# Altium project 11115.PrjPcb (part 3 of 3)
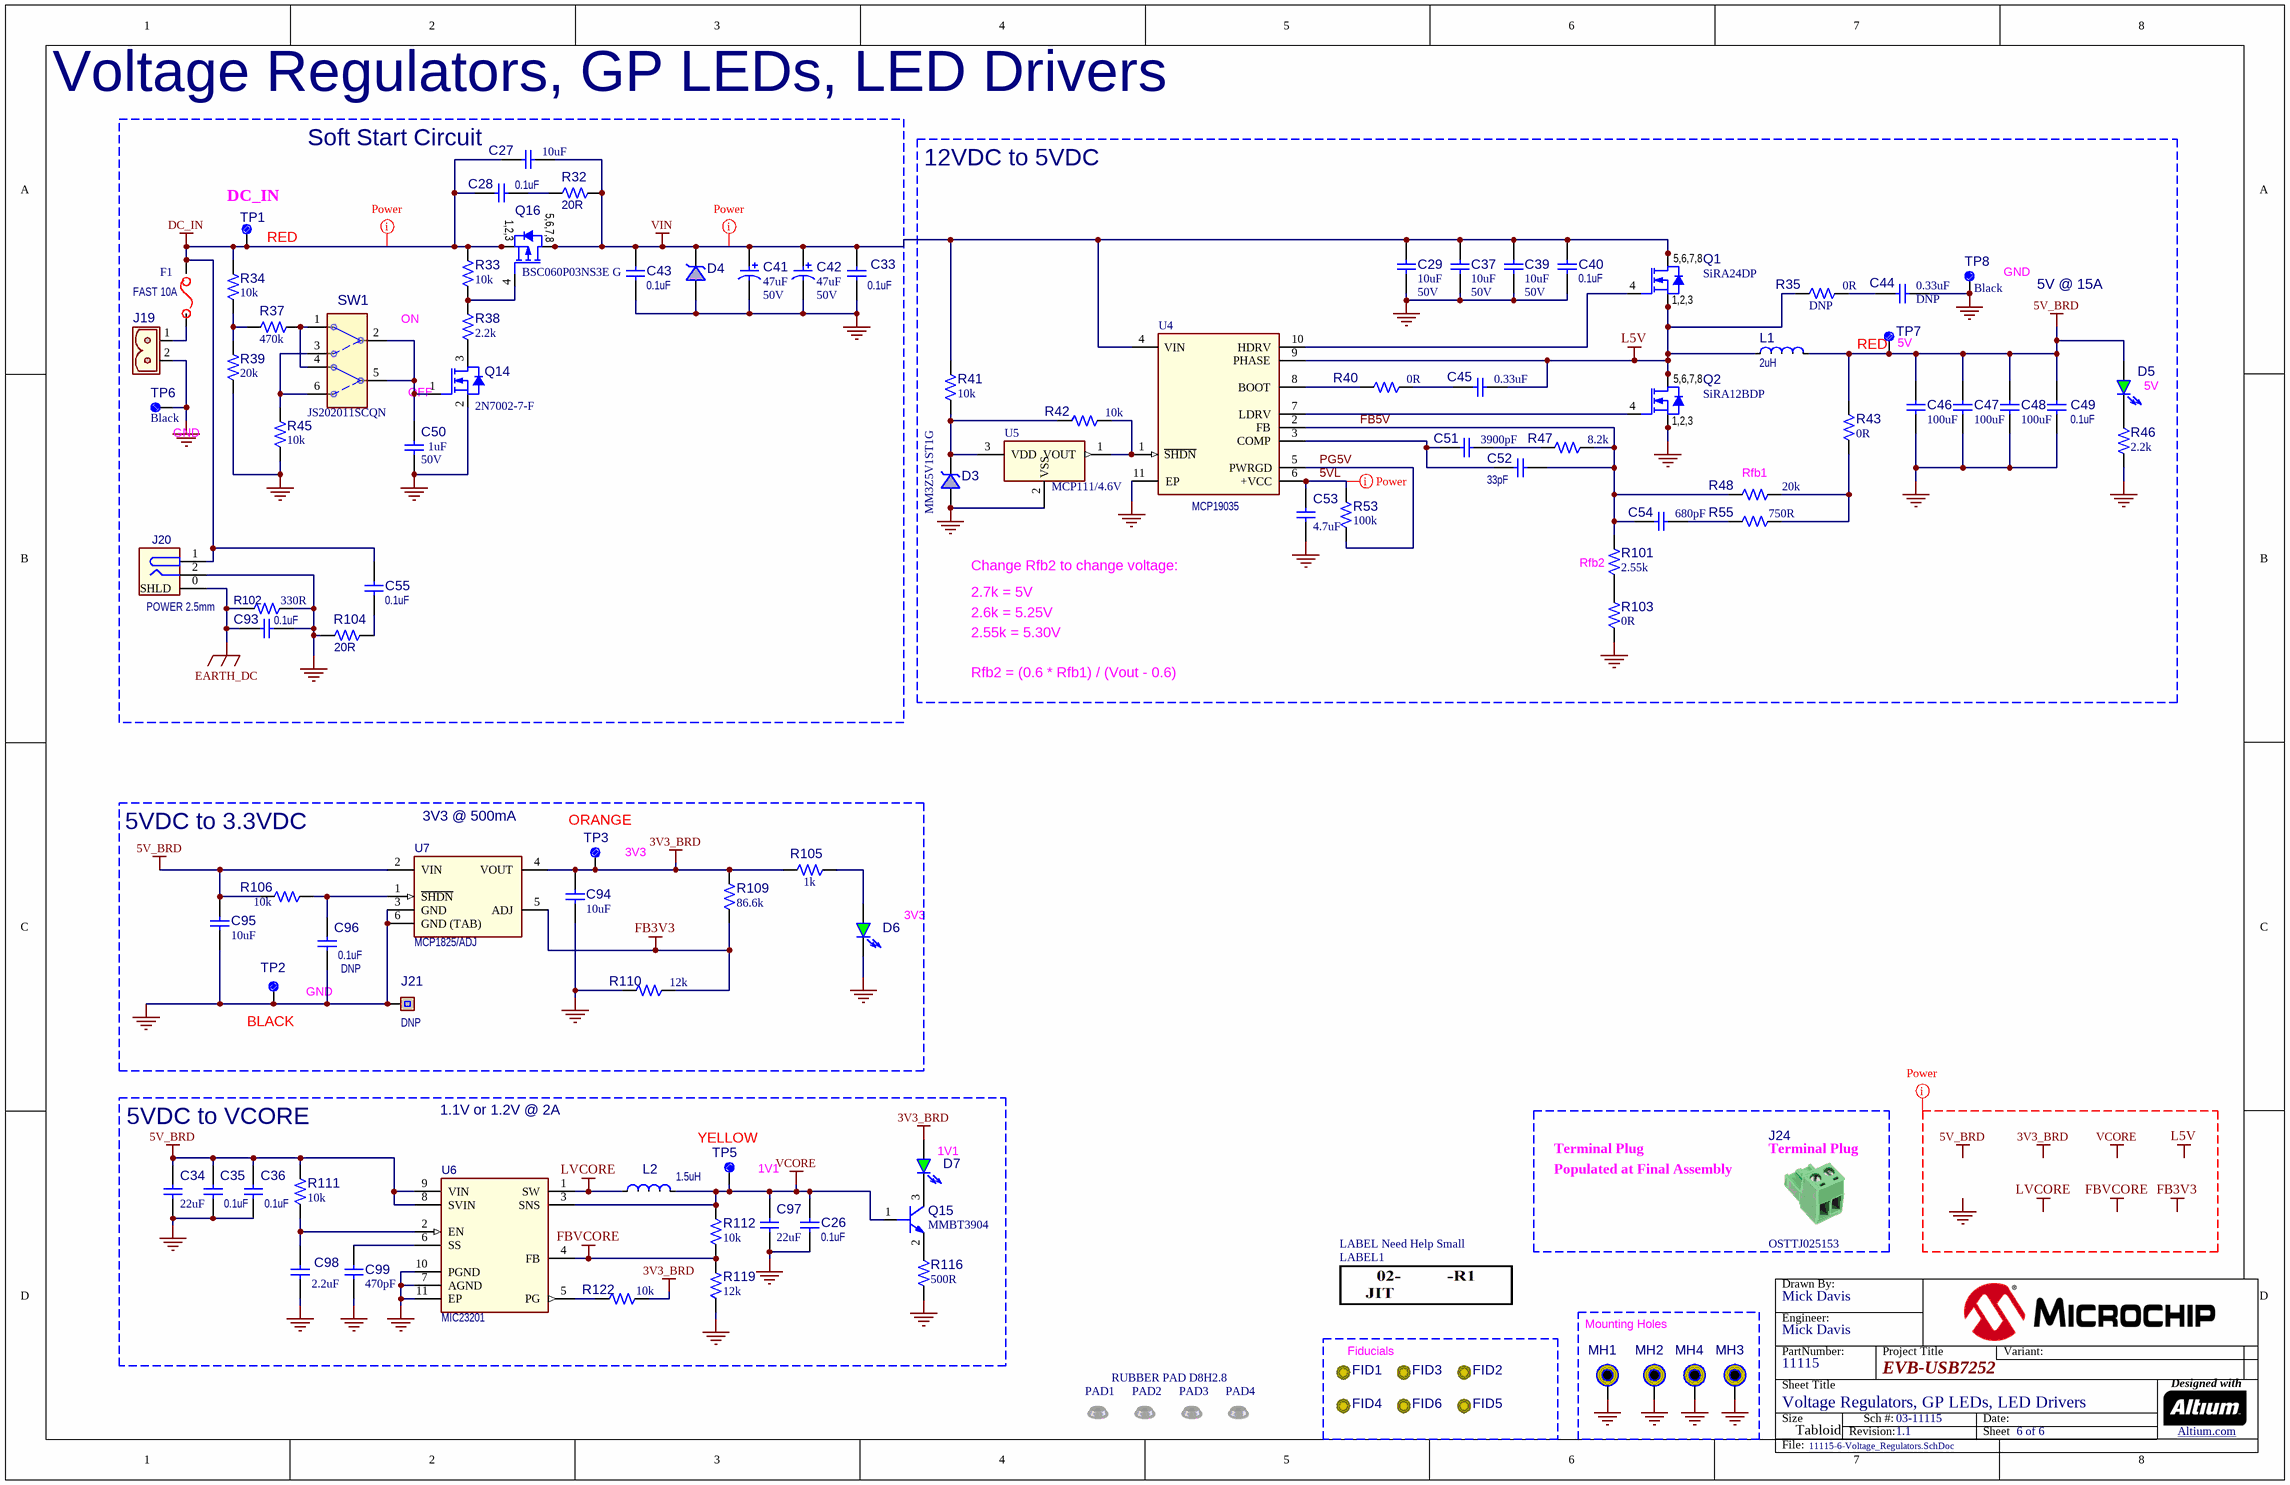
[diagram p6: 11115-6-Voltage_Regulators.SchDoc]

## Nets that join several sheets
3V3_BRD: 11115-2-USB7252 (32 pins), 11115-3-USB-B-Upstream (6 pins), 11115-4-USB-C Downstream 1-2 (D15.2 D16.2), 11115-6-Voltage_Regulators (7 pins)
5V_BRD: 11115-3-USB-B-Upstream (C60.1 J5.10 R58.1 U9.5), 11115-4-USB-C Downstream 1-2 (23 pins), 11115-5-USB-A Downstream 3-4 (13 pins), 11115-6-Voltage_Regulators (17 pins)
GND: 11115-2-USB7252 (39 pins), 11115-3-USB-B-Upstream (17 pins), 11115-4-USB-C Downstream 1-2 (47 pins), 11115-5-USB-A Downstream 3-4 (24 pins), 11115-6-Voltage_Regulators (59 pins)
VCORE: 11115-2-USB7252 (18 pins), 11115-6-Voltage_Regulators (7 pins)
BASIC_CC1_P1: 11115-2-USB7252 (U3.12), 11115-4-USB-C Downstream 1-2 (R2.1 R73.2)
BASIC_CC1_P2: 11115-2-USB7252 (U3.27), 11115-4-USB-C Downstream 1-2 (R68.1 R70.2)
BASIC_CC2_P1: 11115-2-USB7252 (U3.13), 11115-4-USB-C Downstream 1-2 (R67.1 R74.2)
BASIC_CC2_P2: 11115-2-USB7252 (U3.28), 11115-4-USB-C Downstream 1-2 (R1.1 R69.2)
DP1_DISCHARGE: 11115-2-USB7252 (R18.1), 11115-4-USB-C Downstream 1-2 (Q8.1 R85.2)
DP1_VBUS_MON: 11115-2-USB7252 (U3.4), 11115-4-USB-C Downstream 1-2 (C72.1 D16.3 R76.1 R82.2)
DP1_VCONN1: 11115-2-USB7252 (R15.1), 11115-4-USB-C Downstream 1-2 (Q13.1 R94.2)
DP1_VCONN2: 11115-2-USB7252 (R16.1), 11115-4-USB-C Downstream 1-2 (Q12.1 R93.2)
DP2_DISCHARGE: 11115-2-USB7252 (R17.1), 11115-4-USB-C Downstream 1-2 (Q7.1 R92.2)
DP2_VBUS_MON: 11115-2-USB7252 (U3.36), 11115-4-USB-C Downstream 1-2 (C70.1 D15.3 R75.2 R80.1)
DP2_VCONN1: 11115-2-USB7252 (R22.1), 11115-4-USB-C Downstream 1-2 (Q10.1 R90.2)
DP2_VCONN2: 11115-2-USB7252 (R23.1), 11115-4-USB-C Downstream 1-2 (Q11.1 R91.2)
MSTR_I2C_CLK: 11115-2-USB7252 (J13.1 R30.1 R100.1), 11115-3-USB-B-Upstream (J5.12)
MSTR_I2C_DATA: 11115-2-USB7252 (J13.3 R28.1 R99.1), 11115-3-USB-B-Upstream (J5.11)
PF7: 11115-2-USB7252 (U3.48), 11115-3-USB-B-Upstream (J5.15)
PF14: 11115-2-USB7252 (U3.57), 11115-3-USB-B-Upstream (J5.3)
PF19: 11115-2-USB7252 (J10.3 R95.1 U3.66), 11115-3-USB-B-Upstream (J5.4)
PF26: 11115-2-USB7252 (J10.1 R97.1 U3.75), 11115-3-USB-B-Upstream (J5.6)
PF27: 11115-2-USB7252 (U3.76), 11115-3-USB-B-Upstream (J5.1)
PF28: 11115-2-USB7252 (U3.77), 11115-3-USB-B-Upstream (J5.5)
PRT_CTL1: 11115-2-USB7252 (R25.1), 11115-4-USB-C Downstream 1-2 (R7.1 R8.1)
PRT_CTL2: 11115-2-USB7252 (R24.1), 11115-4-USB-C Downstream 1-2 (R9.2 R10.2)
PRT_CTL3: 11115-2-USB7252 (U3.56), 11115-5-USB-A Downstream 3-4 (U2.1 U2.20)
PRT_CTL4: 11115-2-USB7252 (U3.59), 11115-5-USB-A Downstream 3-4 (U2.15 U2.16)
RST_N: 11115-2-USB7252 (5 pins), 11115-3-USB-B-Upstream (J6.2)
SPI_CE/PF20: 11115-2-USB7252 (J14.4), 11115-3-USB-B-Upstream (R118.1 U8.1 U9.2)
SPI_CLK/PF21: 11115-2-USB7252 (U3.68), 11115-3-USB-B-Upstream (J15.4 R115.2 U8.6)
SPI_D2/PF24: 11115-2-USB7252 (U3.72), 11115-3-USB-B-Upstream (J15.1 R49.2)
SPI_D3/PF25: 11115-2-USB7252 (U3.73), 11115-3-USB-B-Upstream (J15.3 R51.2)
SPI_MISO/PF23: 11115-2-USB7252 (U3.71), 11115-3-USB-B-Upstream (R117.2 U8.2)
SPI_MOSI/PF22: 11115-2-USB7252 (J14.1), 11115-3-USB-B-Upstream (J15.2 U8.5)
USB2DN1/PRT_DIS_1_N: 11115-2-USB7252 (U3.6), 11115-4-USB-C Downstream 1-2 (J2.A7 J2.B7)
USB2DN1/PRT_DIS_1_P: 11115-2-USB7252 (U3.5), 11115-4-USB-C Downstream 1-2 (J2.A6 J2.B6)
USB2DN2/PRT_DIS_2_N: 11115-2-USB7252 (U3.30), 11115-4-USB-C Downstream 1-2 (J3.A7 J3.B7)
USB2DN2/PRT_DIS_2_P: 11115-2-USB7252 (U3.29), 11115-4-USB-C Downstream 1-2 (J3.A6 J3.B6)
USB2DN3/PRT_DIS_3_N: 11115-2-USB7252 (U3.82), 11115-5-USB-A Downstream 3-4 (J1.2)
USB2DN3/PRT_DIS_3_P: 11115-2-USB7252 (U3.81), 11115-5-USB-A Downstream 3-4 (J1.3)
USB2DN4/PRT_DIS_4_N: 11115-2-USB7252 (U3.15), 11115-5-USB-A Downstream 3-4 (J4.2)
USB2DN4/PRT_DIS_4_P: 11115-2-USB7252 (U3.14), 11115-5-USB-A Downstream 3-4 (J4.3)
USB2UP_N: 11115-2-USB7252 (U3.90), 11115-3-USB-B-Upstream (J22.2)
USB2UP_P: 11115-2-USB7252 (U3.89), 11115-3-USB-B-Upstream (J22.3)
USB3DN_RX1A_N: 11115-2-USB7252 (U3.11), 11115-4-USB-C Downstream 1-2 (J2.B10)
USB3DN_RX1A_P: 11115-2-USB7252 (U3.10), 11115-4-USB-C Downstream 1-2 (J2.B11)
USB3DN_RX1B_N: 11115-2-USB7252 (U3.19), 11115-4-USB-C Downstream 1-2 (J2.A10)
USB3DN_RX1B_P: 11115-2-USB7252 (U3.20), 11115-4-USB-C Downstream 1-2 (J2.A11)
USB3DN_RX2A_N: 11115-2-USB7252 (U3.35), 11115-4-USB-C Downstream 1-2 (J3.B10)
USB3DN_RX2A_P: 11115-2-USB7252 (U3.34), 11115-4-USB-C Downstream 1-2 (J3.B11)
USB3DN_RX2B_N: 11115-2-USB7252 (U3.40), 11115-4-USB-C Downstream 1-2 (J3.A10)
USB3DN_RX2B_P: 11115-2-USB7252 (U3.41), 11115-4-USB-C Downstream 1-2 (J3.A11)
USB3DN_RX3_N: 11115-2-USB7252 (U3.87), 11115-5-USB-A Downstream 3-4 (J1.5)
USB3DN_RX3_P: 11115-2-USB7252 (U3.86), 11115-5-USB-A Downstream 3-4 (J1.6)
USB3DN_TX1A_N: 11115-2-USB7252 (U3.8), 11115-4-USB-C Downstream 1-2 (C10.1)
USB3DN_TX1A_P: 11115-2-USB7252 (U3.7), 11115-4-USB-C Downstream 1-2 (C9.1)
USB3DN_TX1B_N: 11115-2-USB7252 (U3.16), 11115-4-USB-C Downstream 1-2 (C11.1)
USB3DN_TX1B_P: 11115-2-USB7252 (U3.17), 11115-4-USB-C Downstream 1-2 (C12.1)
USB3DN_TX2A_N: 11115-2-USB7252 (U3.32), 11115-4-USB-C Downstream 1-2 (C15.1)
USB3DN_TX2A_P: 11115-2-USB7252 (U3.31), 11115-4-USB-C Downstream 1-2 (C14.1)
USB3DN_TX2B_N: 11115-2-USB7252 (U3.37), 11115-4-USB-C Downstream 1-2 (C67.1)
USB3DN_TX2B_P: 11115-2-USB7252 (U3.38), 11115-4-USB-C Downstream 1-2 (C66.1)
USB3DN_TX3_N: 11115-2-USB7252 (U3.84), 11115-5-USB-A Downstream 3-4 (C68.1)
USB3DN_TX3_P: 11115-2-USB7252 (U3.83), 11115-5-USB-A Downstream 3-4 (C69.1)
USB3UP_RX_N: 11115-2-USB7252 (U3.94), 11115-3-USB-B-Upstream (J22.9)
USB3UP_RX_P: 11115-2-USB7252 (U3.95), 11115-3-USB-B-Upstream (J22.10)
USB3UP_TX_N: 11115-2-USB7252 (U3.92), 11115-3-USB-B-Upstream (C57.2)
USB3UP_TX_P: 11115-2-USB7252 (U3.91), 11115-3-USB-B-Upstream (C58.2)
VBUS_DET: 11115-2-USB7252 (U3.80), 11115-3-USB-B-Upstream (R54.2 R56.2)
